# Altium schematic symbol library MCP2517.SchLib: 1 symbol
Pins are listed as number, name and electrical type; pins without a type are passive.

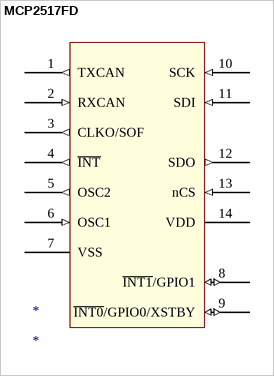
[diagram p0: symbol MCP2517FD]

## MCP2517FD
designator *
footprint SOP14
pins: 1 TXCAN (out), 2 RXCAN (in), 3 CLKO/SOF (out), 4 ~{INT} (out), 5 OSC2 (out), 6 OSC1 (in), 7 VSS (power), 8 ~{INT1}/GPIO1 (io), 9 ~{INT0}/GPIO0/XSTBY (io), 10 SCK (in), 11 SDI (in), 12 SDO (out), 13 nCS (in), 14 VDD (power)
